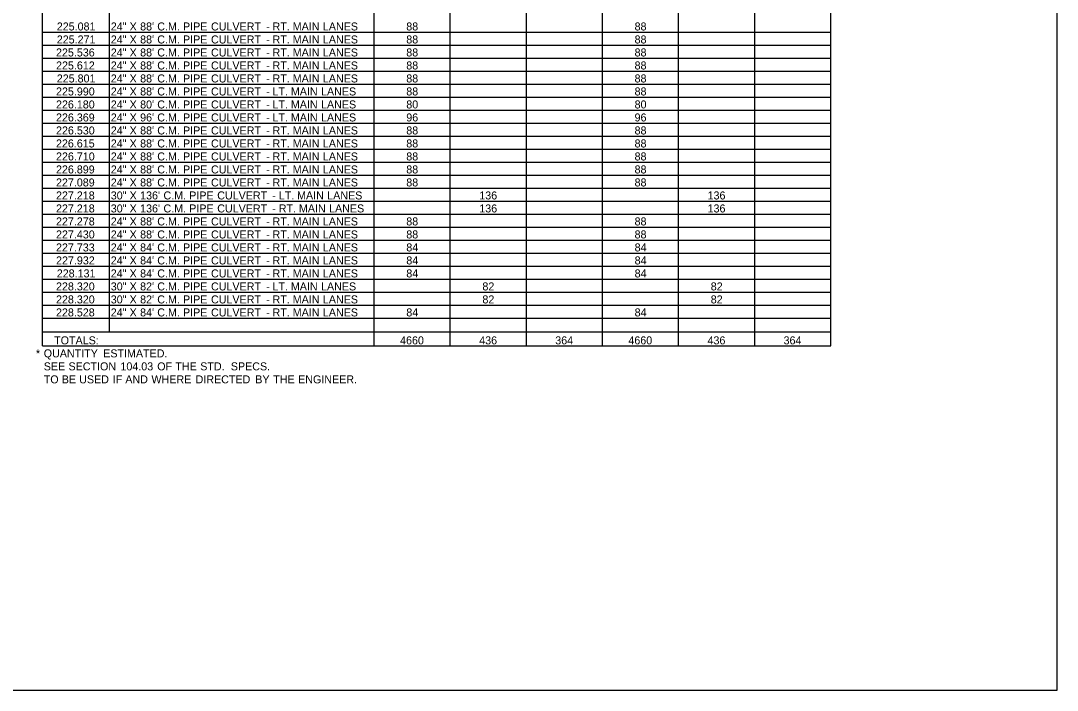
# Model space of a CAD drawing. Extents: x 2261867 to 2275370, y -3124789 to -3122260.
# Drawn here: x 2265138 to 2265915, y -3124774 to -3124272 of the extents above; entities that cross this region are included whole.
import ezdxf

# ---------------------------------------------------------------- set-up
doc = ezdxf.new("R2010")
doc.units = 0
doc.layers.add('DSN_DRFT_Named-Boundary', color=7, linetype='Continuous')
doc.layers.add('DSN_QNTY_Annotation', color=7, linetype='Continuous')

msp = doc.modelspace()

# ---------------------------------------------------------------- linework, layer by layer
at = {"layer": 'DSN_DRFT_Named-Boundary'}
msp.add_lwpolyline([(2264290.05, -3124774.39), (2265915.05, -3124774.39), (2265915.05, -3123775.33), (2264290.05, -3123775.33)], close=True, dxfattribs=at)
at = {"layer": 'DSN_QNTY_Annotation'}
for p, q in [((2265154.48, -3124516.11), (2265154.48, -3123861.39)), ((2265154.48, -3124516.11), (2265154.48, -3123861.39)), ((2265204.69, -3124505.38), (2265204.69, -3123861.39)), ((2265403.1, -3124516.11), (2265403.1, -3123861.39)), ((2265745.33, -3124516.11), (2265745.33, -3123861.39)), ((2265745.33, -3124516.11), (2265745.33, -3123861.39)), ((2265403.1, -3124516.11), (2265403.1, -3123880.89)), ((2265204.69, -3124505.38), (2265204.69, -3123890.64)), ((2265460.14, -3124505.38), (2265460.14, -3123890.64)), ((2265460.14, -3124516.11), (2265460.14, -3123890.64)), ((2265517.18, -3124505.38), (2265517.18, -3123890.64)), ((2265517.18, -3124516.11), (2265517.18, -3123890.64)), ((2265574.22, -3124516.11), (2265574.22, -3123890.64)), ((2265631.25, -3124505.38), (2265631.25, -3123890.64)), ((2265631.25, -3124516.11), (2265631.25, -3123890.64)), ((2265688.29, -3124505.38), (2265688.29, -3123890.64)), ((2265688.29, -3124516.11), (2265688.29, -3123890.64)), ((2265154.48, -3124280.64), (2265745.33, -3124280.64)), ((2265154.48, -3124290.39), (2265745.33, -3124290.39)), ((2265154.48, -3124300.14), (2265745.33, -3124300.14)), ((2265154.48, -3124309.89), (2265745.33, -3124309.89)), ((2265154.48, -3124319.64), (2265745.33, -3124319.64)), ((2265154.48, -3124329.39), (2265745.33, -3124329.39)), ((2265154.48, -3124339.14), (2265745.33, -3124339.14)), ((2265154.48, -3124348.89), (2265745.33, -3124348.89)), ((2265154.48, -3124358.64), (2265745.33, -3124358.64)), ((2265154.48, -3124368.39), (2265745.33, -3124368.39)), ((2265154.48, -3124378.14), (2265745.33, -3124378.14)), ((2265154.48, -3124387.89), (2265745.33, -3124387.89)), ((2265154.48, -3124397.64), (2265745.33, -3124397.64)), ((2265154.48, -3124407.39), (2265745.33, -3124407.39)), ((2265154.48, -3124417.14), (2265745.33, -3124417.14)), ((2265154.48, -3124426.89), (2265745.33, -3124426.89)), ((2265154.48, -3124436.64), (2265745.33, -3124436.64)), ((2265154.48, -3124446.39), (2265745.33, -3124446.39)), ((2265154.48, -3124456.14), (2265745.33, -3124456.14)), ((2265154.48, -3124465.89), (2265745.33, -3124465.89)), ((2265154.48, -3124475.64), (2265745.33, -3124475.64)), ((2265154.48, -3124485.39), (2265745.33, -3124485.39)), ((2265154.48, -3124495.14), (2265745.33, -3124495.14)), ((2265154.48, -3124505.38), (2265745.33, -3124505.38)), ((2265154.48, -3124505.38), (2265745.33, -3124505.38)), ((2265154.48, -3124516.11), (2265745.33, -3124516.11))]:
    msp.add_line(p, q, dxfattribs=at)

# ---------------------------------------------------------------- texts
for s, p in [('225.081', (2265165.21, -3124279.44)), ('24"', (2265205.67, -3124279.44)), (' X', (2265217.57, -3124279.44)), (" 88'", (2265225.44, -3124279.44)), (' C.M.', (2265238.29, -3124279.44)), (' PIPE', (2265257.58, -3124279.44)), (' CULVERT', (2265278.57, -3124279.44)), (' -', (2265319.86, -3124279.44)), (' RT.', (2265324.71, -3124279.44)), (' MAIN', (2265339.82, -3124279.44)), (' LANES', (2265362.42, -3124279.44)), ('88', (2265427.15, -3124279.44)), ('88', (2265598.26, -3124279.44)), ('225.271', (2265165.21, -3124289.19)), ('24"', (2265205.67, -3124289.19)), (' X', (2265217.57, -3124289.19)), (" 88'", (2265225.44, -3124289.19)), (' C.M.', (2265238.29, -3124289.19)), (' PIPE', (2265257.58, -3124289.19)), (' CULVERT', (2265278.57, -3124289.19)), (' -', (2265319.86, -3124289.19)), (' RT.', (2265324.71, -3124289.19)), (' MAIN', (2265339.82, -3124289.19)), (' LANES', (2265362.42, -3124289.19)), ('88', (2265427.15, -3124289.19)), ('88', (2265598.26, -3124289.19)), ('225.536', (2265164.63, -3124298.94)), ('24"', (2265205.67, -3124298.94)), (' X', (2265217.57, -3124298.94)), (" 88'", (2265225.44, -3124298.94)), (' C.M.', (2265238.29, -3124298.94)), (' PIPE', (2265257.58, -3124298.94)), (' CULVERT', (2265278.57, -3124298.94)), (' RT.', (2265324.71, -3124298.94)), (' MAIN', (2265339.82, -3124298.94)), (' LANES', (2265362.42, -3124298.94)), ('88', (2265427.15, -3124298.94)), ('88', (2265598.26, -3124298.94)), (' -', (2265319.86, -3124298.94)), ('225.612', (2265164.66, -3124308.69)), ('24"', (2265205.67, -3124308.69)), (' X', (2265217.57, -3124308.69)), (" 88'", (2265225.44, -3124308.69)), (' C.M.', (2265238.29, -3124308.69)), (' PIPE', (2265257.58, -3124308.69)), (' CULVERT', (2265278.57, -3124308.69)), (' -', (2265319.86, -3124308.69)), (' RT.', (2265324.71, -3124308.69)), (' MAIN', (2265339.82, -3124308.69)), (' LANES', (2265362.42, -3124308.69)), ('88', (2265427.15, -3124308.69)), ('88', (2265598.26, -3124308.69)), ('225.801', (2265165.21, -3124318.44)), ('24"', (2265205.67, -3124318.44)), (' X', (2265217.57, -3124318.44)), (" 88'", (2265225.44, -3124318.44)), (' C.M.', (2265238.29, -3124318.44)), (' PIPE', (2265257.58, -3124318.44)), (' CULVERT', (2265278.57, -3124318.44)), (' -', (2265319.86, -3124318.44)), (' RT.', (2265324.71, -3124318.44)), (' MAIN', (2265339.82, -3124318.44)), (' LANES', (2265362.42, -3124318.44)), ('88', (2265427.15, -3124318.44)), ('88', (2265598.26, -3124318.44)), ('225.990', (2265164.64, -3124328.19)), ('24"', (2265205.67, -3124328.19)), (' X', (2265217.57, -3124328.19)), (" 88'", (2265225.44, -3124328.19)), (' C.M.', (2265238.29, -3124328.19)), (' PIPE', (2265257.58, -3124328.19)), (' CULVERT', (2265278.57, -3124328.19)), (' -', (2265319.86, -3124328.19)), (' LT.', (2265324.71, -3124328.19)), (' MAIN', (2265338.42, -3124328.19)), (' LANES', (2265361.02, -3124328.19)), ('88', (2265427.15, -3124328.19)), ('88', (2265598.26, -3124328.19)), ('226.180', (2265164.64, -3124337.94)), ('24"', (2265205.67, -3124337.94)), (' X', (2265217.57, -3124337.94)), (" 80'", (2265225.44, -3124337.94)), (' C.M.', (2265238.29, -3124337.94)), (' PIPE', (2265257.58, -3124337.94)), (' CULVERT', (2265278.57, -3124337.94)), (' LT.', (2265324.71, -3124337.94)), (' MAIN', (2265338.42, -3124337.94)), (' LANES', (2265361.02, -3124337.94)), ('80', (2265427.16, -3124337.94)), ('80', (2265598.28, -3124337.94)), (' -', (2265319.86, -3124337.94)), ('226.369', (2265164.63, -3124347.69)), ('24"', (2265205.67, -3124347.69)), (' X', (2265217.57, -3124347.69)), (" 96'", (2265225.44, -3124347.69)), (' C.M.', (2265238.29, -3124347.69)), (' PIPE', (2265257.58, -3124347.69)), (' CULVERT', (2265278.57, -3124347.69)), (' -', (2265319.86, -3124347.69)), (' LT.', (2265324.71, -3124347.69)), (' MAIN', (2265338.42, -3124347.69)), (' LANES', (2265361.02, -3124347.69)), ('96', (2265427.15, -3124347.69)), ('96', (2265598.26, -3124347.69)), ('226.530', (2265164.64, -3124357.44)), ('24"', (2265205.67, -3124357.44)), (' X', (2265217.57, -3124357.44)), (" 88'", (2265225.44, -3124357.44)), (' C.M.', (2265238.29, -3124357.44)), (' PIPE', (2265257.58, -3124357.44)), (' CULVERT', (2265278.57, -3124357.44)), (' -', (2265319.86, -3124357.44)), (' RT.', (2265324.71, -3124357.44)), (' MAIN', (2265339.82, -3124357.44)), (' LANES', (2265362.42, -3124357.44)), ('88', (2265427.15, -3124357.44)), ('88', (2265598.26, -3124357.44)), ('226.615', (2265164.61, -3124367.19)), ('24"', (2265205.67, -3124367.19)), (' X', (2265217.57, -3124367.19)), (" 88'", (2265225.44, -3124367.19)), (' C.M.', (2265238.29, -3124367.19)), (' PIPE', (2265257.58, -3124367.19)), (' CULVERT', (2265278.57, -3124367.19)), (' -', (2265319.86, -3124367.19)), (' RT.', (2265324.71, -3124367.19)), (' MAIN', (2265339.82, -3124367.19)), (' LANES', (2265362.42, -3124367.19)), ('88', (2265427.15, -3124367.19)), ('88', (2265598.26, -3124367.19)), ('226.710', (2265164.64, -3124376.94)), ('24"', (2265205.67, -3124376.94)), (' X', (2265217.57, -3124376.94)), (" 88'", (2265225.44, -3124376.94)), (' C.M.', (2265238.29, -3124376.94)), (' PIPE', (2265257.58, -3124376.94)), (' CULVERT', (2265278.57, -3124376.94)), (' RT.', (2265324.71, -3124376.94)), (' MAIN', (2265339.82, -3124376.94)), (' LANES', (2265362.42, -3124376.94)), ('88', (2265427.15, -3124376.94)), ('88', (2265598.26, -3124376.94)), (' -', (2265319.86, -3124376.94)), ('226.899', (2265164.63, -3124386.69)), ('24"', (2265205.67, -3124386.69)), (' X', (2265217.57, -3124386.69)), (" 88'", (2265225.44, -3124386.69)), (' C.M.', (2265238.29, -3124386.69)), (' PIPE', (2265257.58, -3124386.69)), (' CULVERT', (2265278.57, -3124386.69)), (' -', (2265319.86, -3124386.69)), (' RT.', (2265324.71, -3124386.69)), (' MAIN', (2265339.82, -3124386.69)), (' LANES', (2265362.42, -3124386.69)), ('88', (2265427.15, -3124386.69)), ('88', (2265598.26, -3124386.69)), ('227.089', (2265164.63, -3124396.44)), ('24"', (2265205.67, -3124396.44)), (' X', (2265217.57, -3124396.44)), (" 88'", (2265225.44, -3124396.44)), (' C.M.', (2265238.29, -3124396.44)), (' PIPE', (2265257.58, -3124396.44)), (' CULVERT', (2265278.57, -3124396.44)), (' -', (2265319.86, -3124396.44)), (' RT.', (2265324.71, -3124396.44)), (' MAIN', (2265339.82, -3124396.44)), (' LANES', (2265362.42, -3124396.44)), ('88', (2265427.15, -3124396.44)), ('88', (2265598.26, -3124396.44)), ('227.218', (2265164.63, -3124406.19)), ('30"', (2265205.67, -3124406.19)), (' X', (2265217.57, -3124406.19)), (" 136'", (2265225.44, -3124406.19)), (' C.M.', (2265242.95, -3124406.19)), (' PIPE', (2265262.24, -3124406.19)), (' CULVERT', (2265283.23, -3124406.19)), (' LT.', (2265329.37, -3124406.19)), (' MAIN', (2265343.08, -3124406.19)), (' LANES', (2265365.68, -3124406.19)), ('136', (2265481.86, -3124406.19)), ('136', (2265652.97, -3124406.19)), ('227.218', (2265164.63, -3124415.94)), ('30"', (2265205.67, -3124415.94)), (' X', (2265217.57, -3124415.94)), (" 136'", (2265225.44, -3124415.94)), (' C.M.', (2265242.95, -3124415.94)), (' PIPE', (2265262.24, -3124415.94)), (' CULVERT', (2265283.23, -3124415.94)), (' -', (2265324.52, -3124406.19)), (' RT.', (2265329.37, -3124415.94)), (' MAIN', (2265344.48, -3124415.94)), (' LANES', (2265367.08, -3124415.94)), ('136', (2265481.86, -3124415.94)), ('136', (2265652.97, -3124415.94)), (' -', (2265324.52, -3124415.94)), ('227.278', (2265164.63, -3124425.69)), ('24"', (2265205.67, -3124425.69)), (' X', (2265217.57, -3124425.69)), (" 88'", (2265225.44, -3124425.69)), (' C.M.', (2265238.29, -3124425.69)), (' PIPE', (2265257.58, -3124425.69)), (' CULVERT', (2265278.57, -3124425.69)), (' -', (2265319.86, -3124425.69)), (' RT.', (2265324.71, -3124425.69)), (' MAIN', (2265339.82, -3124425.69)), (' LANES', (2265362.42, -3124425.69)), ('88', (2265427.15, -3124425.69)), ('88', (2265598.26, -3124425.69)), ('227.430', (2265164.64, -3124435.44)), ('24"', (2265205.67, -3124435.44)), (' X', (2265217.57, -3124435.44)), (" 88'", (2265225.44, -3124435.44)), (' C.M.', (2265238.29, -3124435.44)), (' PIPE', (2265257.58, -3124435.44)), (' CULVERT', (2265278.57, -3124435.44)), (' -', (2265319.86, -3124435.44)), (' RT.', (2265324.71, -3124435.44)), (' MAIN', (2265339.82, -3124435.44)), (' LANES', (2265362.42, -3124435.44)), ('88', (2265427.15, -3124435.44)), ('88', (2265598.26, -3124435.44)), ('227.733', (2265164.63, -3124445.19)), ('24"', (2265205.67, -3124445.19)), (' X', (2265217.57, -3124445.19)), (" 84'", (2265225.44, -3124445.19)), (' C.M.', (2265238.29, -3124445.19)), (' PIPE', (2265257.58, -3124445.19)), (' CULVERT', (2265278.57, -3124445.19)), (' RT.', (2265324.71, -3124445.19)), (' MAIN', (2265339.82, -3124445.19)), (' LANES', (2265362.42, -3124445.19)), ('84', (2265427.17, -3124445.19)), ('84', (2265598.28, -3124445.19)), ('227.932', (2265164.66, -3124454.94)), ('24"', (2265205.67, -3124454.94)), (' X', (2265217.57, -3124454.94)), (" 84'", (2265225.44, -3124454.94)), (' C.M.', (2265238.29, -3124454.94)), (' PIPE', (2265257.58, -3124454.94)), (' CULVERT', (2265278.57, -3124454.94)), (' -', (2265319.86, -3124445.19)), (' RT.', (2265324.71, -3124454.94)), (' MAIN', (2265339.82, -3124454.94)), (' LANES', (2265362.42, -3124454.94)), ('84', (2265427.17, -3124454.94)), ('84', (2265598.28, -3124454.94)), (' -', (2265319.86, -3124454.94)), ('228.131', (2265165.21, -3124464.69)), ('24"', (2265205.67, -3124464.69)), (' X', (2265217.57, -3124464.69)), (" 84'", (2265225.44, -3124464.69)), (' C.M.', (2265238.29, -3124464.69)), (' PIPE', (2265257.58, -3124464.69)), (' CULVERT', (2265278.57, -3124464.69)), (' -', (2265319.86, -3124464.69)), (' RT.', (2265324.71, -3124464.69)), (' MAIN', (2265339.82, -3124464.69)), (' LANES', (2265362.42, -3124464.69)), ('84', (2265427.17, -3124464.69)), ('84', (2265598.28, -3124464.69)), ('228.320', (2265164.64, -3124474.44)), ('30"', (2265205.67, -3124474.44)), (' X', (2265217.57, -3124474.44)), (" 82'", (2265225.44, -3124474.44)), (' C.M.', (2265238.29, -3124474.44)), (' PIPE', (2265257.58, -3124474.44)), (' CULVERT', (2265278.57, -3124474.44)), (' -', (2265319.86, -3124474.44)), (' LT.', (2265324.71, -3124474.44)), (' MAIN', (2265338.42, -3124474.44)), (' LANES', (2265361.02, -3124474.44)), ('82', (2265484.22, -3124474.44)), ('82', (2265655.33, -3124474.44)), ('228.320', (2265164.64, -3124484.19)), ('30"', (2265205.67, -3124484.19)), (' X', (2265217.57, -3124484.19)), (" 82'", (2265225.44, -3124484.19)), (' C.M.', (2265238.29, -3124484.19)), (' PIPE', (2265257.58, -3124484.19)), (' CULVERT', (2265278.57, -3124484.19)), (' RT.', (2265324.71, -3124484.19)), (' MAIN', (2265339.82, -3124484.19)), (' LANES', (2265362.42, -3124484.19)), ('82', (2265484.22, -3124484.19)), ('82', (2265655.33, -3124484.19)), ('228.528', (2265164.63, -3124493.94)), ('24"', (2265205.67, -3124493.94)), (' X', (2265217.57, -3124493.94)), (" 84'", (2265225.44, -3124493.94)), (' C.M.', (2265238.29, -3124493.94)), (' PIPE', (2265257.58, -3124493.94)), (' CULVERT', (2265278.57, -3124493.94)), (' -', (2265319.86, -3124484.19)), (' RT.', (2265324.71, -3124493.94)), (' MAIN', (2265339.82, -3124493.94)), (' LANES', (2265362.42, -3124493.94)), ('84', (2265427.17, -3124493.94)), ('84', (2265598.28, -3124493.94)), (' -', (2265319.86, -3124493.94)), ('TOTALS:', (2265163.25, -3124514.91)), ('4660', (2265422.51, -3124514.91)), ('436', (2265481.82, -3124514.91)), ('364', (2265538.8, -3124514.91)), ('4660', (2265593.62, -3124514.91)), ('436', (2265652.93, -3124514.91)), ('364', (2265709.92, -3124514.91)), ('*', (2265149.6, -3124524.66)), ('QUANTITY', (2265155.45, -3124524.66)), (' ESTIMATED.', (2265197.78, -3124524.66)), ('SEE', (2265155.45, -3124534.41)), (' SECTION', (2265171.78, -3124534.41)), (' 104.03', (2265210.69, -3124534.41)), (' OF', (2265238.27, -3124534.41)), (' THE', (2265251.86, -3124534.41)), (' STD.', (2265270.51, -3124534.41)), ('  SPECS.', (2265291.2, -3124534.41)), ('TO', (2265155.45, -3124544.16)), (' BE', (2265166.72, -3124544.16)), (' USED', (2265179.79, -3124544.16)), (' IF', (2265204.96, -3124544.16)), (' AND', (2265214.36, -3124544.16)), (' WHERE', (2265233.94, -3124544.16)), (' DIRECTED', (2265267.03, -3124544.16)), (' BY', (2265311.76, -3124544.16)), (' THE', (2265325.21, -3124544.16)), (' ENGINEER.', (2265343.86, -3124544.16))]:
    msp.add_text(s, height=6, dxfattribs=at).set_placement(p)

doc.saveas('drawing.dxf')
